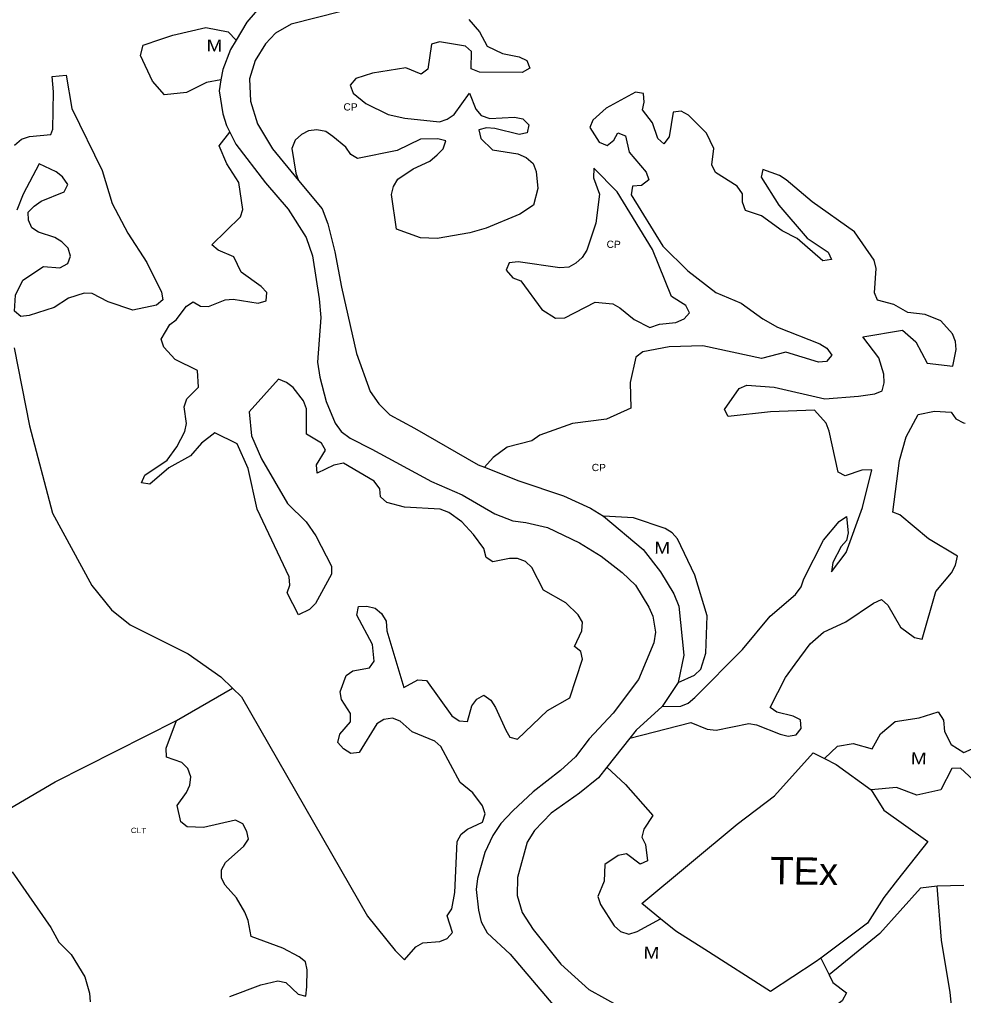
# Model space of a CAD drawing. Extents: x 713589 to 726391, y 7177764 to 7191819.
# Drawn here: x 717458 to 718290, y 7181104 to 7181963 of the extents above; entities that cross this region are included whole.
import ezdxf
from ezdxf.enums import TextEntityAlignment as Align

# ---------------------------------------------------------------- set-up
doc = ezdxf.new("R2010")
doc.units = 0
doc.header["$LTSCALE"] = 2.6
doc.layers.add('63', color=7, linetype='Continuous', lineweight=25)

msp = doc.modelspace()

# ---------------------------------------------------------------- linework, layer by layer
at = {"layer": '63'}
for p, q in [((718038.52, 7181379.7), (718024.45, 7181358.68)), ((717596.72, 7181346.37), (717646, 7181374.88)), ((717995.75, 7181330.77), (717975.51, 7181305.21)), ((718163.9, 7181137.12), (718171.33, 7181122.3))]:
    msp.add_line(p, q, dxfattribs=at)
for points in [[(717832.29, 7182049.62), (717822.19, 7182036.26), (717808.38, 7182023.48), (717791.72, 7182013.22), (717747.47, 7182003.66), (717710.05, 7181989.56), (717687, 7181983.32), (717671.45, 7181976), (717658.76, 7181961.01), (717649.2, 7181945.23)], [(717741.68, 7181970.44), (717697.69, 7181959.42), (717683.97, 7181951.56), (717674.94, 7181942.01), (717665.85, 7181927.27), (717660.97, 7181911.4), (717661.78, 7181891.57), (717667.94, 7181871.61), (717681.14, 7181849.59), (717704.26, 7181821.83)], [(717854.24, 7181963.52), (717863.45, 7181952.66), (717870.36, 7181940.15), (717883.85, 7181933.57), (717898.33, 7181930.61), (717905.24, 7181927.31), (717907.87, 7181920.73), (717900.96, 7181916.79), (717863.44, 7181917.12), (717856.2, 7181920.08), (717856.53, 7181935.22), (717851.27, 7181940.16), (717828.24, 7181943.78), (717821.32, 7181941.81), (717818.03, 7181919.76), (717812.11, 7181915.48), (717798.62, 7181921.08), (717769.33, 7181916.15), (717754.52, 7181911.55), (717749.58, 7181905.62), (717752.21, 7181898.71), (717763.4, 7181889.5), (717783.14, 7181879.95), (717797.62, 7181876.66), (717828.22, 7181873.36), (717835.13, 7181875.66), (717841.06, 7181879.94), (717854.55, 7181898.69), (717860.14, 7181884.54), (717865.08, 7181878.95), (717872.65, 7181876.31), (717894.37, 7181877.63), (717901.61, 7181875.98), (717906.87, 7181870.71), (717905.55, 7181863.8), (717898.31, 7181862.16), (717876.92, 7181867.43), (717869.69, 7181868.09), (717862.77, 7181866.44), (717864.75, 7181858.88), (717874.95, 7181848.67), (717897.32, 7181845.38), (717904.56, 7181842.09), (717910.81, 7181836.82), (717913.44, 7181829.58), (717914.76, 7181814.77), (717911.14, 7181799.96), (717898.96, 7181792.07), (717869.34, 7181779.9), (717854.86, 7181775.62), (717826.23, 7181770.69), (717811.42, 7181771.35), (717790.36, 7181778.92), (717786.09, 7181809.53), (717787.74, 7181816.44), (717791.69, 7181823.02), (717805.18, 7181831.9), (717819.66, 7181838.81)], [(717635.89, 7181910.36), (717623.2, 7181908.13), (717605.42, 7181899.25), (717586.01, 7181897.28), (717575.48, 7181909.13), (717564.95, 7181931.84), (717567.26, 7181941.05), (717582.95, 7181946.14), (717593.59, 7181949.6), (717622.55, 7181956.51), (717642.29, 7181952.55), (717649.2, 7181945.23)], [(717649.2, 7181945.23), (717644.23, 7181937.01), (717637.44, 7181919.46), (717635.89, 7181910.36)], [(717454.18, 7181852.88), (717460.1, 7181858.14), (717467.34, 7181860.44), (717486, 7181862.13), (717487.94, 7181867.02), (717488.28, 7181899.93), (717487.14, 7181913.35), (717499.48, 7181914.47), (717504.53, 7181885.12), (717531.17, 7181830.49), (717540.05, 7181801.53), (717553.87, 7181775.53), (717570.65, 7181749.53), (717583.48, 7181723.53), (717584.79, 7181716.62), (717579.2, 7181712.01), (717558.14, 7181707.74), (717536.42, 7181714.98), (717522.6, 7181722.22), (717515.36, 7181722.55), (717501.54, 7181718.28), (717489.03, 7181710.05), (717466.98, 7181702.82), (717459.74, 7181702.16), (717454.15, 7181706.77)], [(717635.89, 7181910.36), (717634.26, 7181900.8), (717637.46, 7181880.44), (717640.74, 7181870.08), (717643.58, 7181864.35)], [(718024.45, 7181358.68), (718040.71, 7181358.99), (718047.29, 7181361.62), (718053.22, 7181366.55), (718095.02, 7181409), (718119.37, 7181438.28), (718141.75, 7181457.36), (718146.69, 7181463.94), (718149, 7181471.18), (718166.44, 7181505.07), (718180.27, 7181521.52), (718186.52, 7181525.8), (718188.16, 7181511.65), (718186.52, 7181504.74), (718181.91, 7181499.47), (718174.67, 7181485.33), (718173.36, 7181477.27), (718186.34, 7181494.25), (718200.6, 7181533.87), (718208.83, 7181566.95), (718200.02, 7181566.6), (718185.54, 7181561.67), (718179.29, 7181564.96), (718171.4, 7181601.16), (718168.76, 7181608.07), (718158.57, 7181619.59), (718119.73, 7181617.95), (718082.55, 7181614.01), (718079.26, 7181620.26), (718092.1, 7181638.69), (718099.01, 7181641.65), (718123.03, 7181639.67), (718167.45, 7181629.46), (718197.07, 7181631.76), (718211.55, 7181634.06), (718218.13, 7181636.69), (718219.78, 7181643.6), (718219.45, 7181651.17), (718215.17, 7181665.65), (718201.12, 7181684.16), (718235.91, 7181690), (718247.75, 7181679.8), (718257.62, 7181661.04), (718280.21, 7181658.36), (718283.29, 7181672.88), (718282.64, 7181680.12), (718280, 7181686.7), (718269.8, 7181698.22), (718255.98, 7181703.81), (718240.52, 7181705.46), (718228.34, 7181712.7), (718213.87, 7181716.33), (718211.23, 7181722.91), (718212.88, 7181744.3), (718210.91, 7181751.54), (718193.8, 7181776.55), (718156.29, 7181802.88), (718133.59, 7181822.3), (718127.67, 7181826.25), (718112.86, 7181831.52), (718111.54, 7181824.61), (718127.01, 7181799.93), (718152.01, 7181770.96), (718170.44, 7181758.78), (718173.4, 7181752.2), (718165.83, 7181750.89), (718143.13, 7181770.64), (718129.96, 7181777.55), (718111.87, 7181790.71), (718097.72, 7181795.32), (718095.09, 7181802.56), (718095.09, 7181810.13), (718090.48, 7181816.71), (718071.4, 7181828.89), (718068.11, 7181835.48), (718069.76, 7181849.95), (718063.51, 7181863.45), (718047.39, 7181879.25), (718041.13, 7181882.87), (718033.89, 7181881.88), (718030.6, 7181860.16), (718025.66, 7181853.91), (718020.4, 7181858.85), (718015.79, 7181872.67), (718006.91, 7181883.86), (718008.56, 7181890.77), (718007.9, 7181898.34), (718000.99, 7181899.66), (717974.99, 7181885.51), (717963.14, 7181874.98), (717960.51, 7181868.4), (717968.73, 7181855.57), (717975.97, 7181852.6), (717981.9, 7181857.21), (717985.19, 7181863.79)], [(717819.66, 7181838.81), (717826.24, 7181844.4), (717831.51, 7181849.67), (717833.81, 7181856.58), (717826.9, 7181858.55), (717811.44, 7181858.23), (717791.03, 7181848.03), (717756.15, 7181841.12), (717750.23, 7181844.75), (717745.95, 7181851), (717734.44, 7181860.54), (717728.18, 7181864.82), (717720.29, 7181866.47), (717713.05, 7181865.48), (717706.79, 7181862.19), (717701.2, 7181857.26), (717698.24, 7181850.02), (717701.85, 7181828.3), (717704.26, 7181821.83)], [(717724.3, 7181590.56), (717711.13, 7181598.46), (717711.14, 7181620.84), (717708.51, 7181627.75), (717699.3, 7181639.6), (717693.7, 7181643.88), (717686.46, 7181646.84), (717660.66, 7181618.17), (717662.76, 7181596.82), (717671.64, 7181576.75), (717694.34, 7181537.26), (717710.79, 7181521.13), (717719.35, 7181508.95), (717733.16, 7181482.3), (717733.16, 7181475.06), (717719.01, 7181449.39), (717713.74, 7181444.13), (717704.25, 7181439.48), (717694.2, 7181458.8), (717696.63, 7181465.52), (717695.98, 7181472.76), (717667.69, 7181532.33), (717659.79, 7181568.2), (717650.26, 7181589.92), (717630.51, 7181599.46), (717618.66, 7181590.58), (717609.12, 7181579.39), (717590.03, 7181568.87), (717573.25, 7181554.39), (717566.01, 7181555.71), (717568.97, 7181562.29), (717588.39, 7181575.45), (717596.95, 7181587.29), (717604.19, 7181600.78), (717605.51, 7181607.69), (717603.53, 7181622.5), (717605.84, 7181629.41), (717616.04, 7181639.94), (717615.06, 7181654.42), (717595.64, 7181664.3), (717585.44, 7181675.16), (717583.14, 7181682.07), (717590.71, 7181694.9), (717596.31, 7181699.18), (717605.52, 7181711.02), (717611.45, 7181714.97), (717617.7, 7181711.02), (717624.94, 7181710.69), (717639.42, 7181716.61), (717646.66, 7181717.27), (717668.71, 7181713.64), (717675.62, 7181715.95), (717676.28, 7181723.18), (717671.34, 7181728.45), (717653.57, 7181740.96), (717647.32, 7181754.45), (717633.5, 7181760.38), (717627.91, 7181764.99), (717653.12, 7181789.85), (717655.23, 7181796.24), (717651.61, 7181819.94), (717641.08, 7181836.39), (717634.18, 7181852.19), (717643.58, 7181864.35)], [(717643.58, 7181864.35), (717648.82, 7181853.77), (717674.97, 7181819.65), (717694.93, 7181796.51), (717710.79, 7181771.67), (717716.4, 7181755.58), (717722.19, 7181717.47), (717723.71, 7181701.14), (717720.98, 7181661.71), (717722.77, 7181648.68), (717728.5, 7181627.23), (717736.53, 7181608.1), (717741.57, 7181600.83), (717749.58, 7181594.87), (717768.73, 7181585.2), (717821.23, 7181556.78), (717848.36, 7181545.02), (717877.01, 7181528.29), (717892.85, 7181522.26), (717904.26, 7181520.77), (717923.41, 7181516.31), (717951.6, 7181502.76), (717970.6, 7181491.17), (717989.16, 7181476.57), (718000.84, 7181465.35), (718012.5, 7181445.98), (718016.05, 7181438.19), (718018.57, 7181424.21), (718017.07, 7181414.78), (718003.55, 7181382.41), (717981.18, 7181352.88), (717960.17, 7181330.2), (717948.16, 7181314.33), (717934.81, 7181302.36), (717910.83, 7181283.44), (717892.76, 7181266.81), (717882.37, 7181255.52), (717875.27, 7181244.97), (717868.14, 7181230.18), (717861.62, 7181207.13), (717860.52, 7181197.61), (717862.6, 7181179.22), (717865.02, 7181169.2), (717870.31, 7181159.52), (717890.61, 7181140.52), (717932.94, 7181090.31)], [(717985.19, 7181863.79), (717992.1, 7181861.16), (717995.39, 7181846.68), (718010.19, 7181829.23), (718012.49, 7181822.32), (718006.24, 7181817.39), (717998.34, 7181816.73), (717997.03, 7181809.16), (718024.99, 7181764.07), (718047.03, 7181742.35), (718071.71, 7181723.26), (718093.75, 7181713.71), (718112.84, 7181699.89), (718126, 7181692.65), (718163.18, 7181677.83), (718169.43, 7181674.21), (718173.71, 7181667.96), (718169.1, 7181662.37), (718161.86, 7181661.71), (718133.24, 7181670.6), (718111.85, 7181665.01), (718060.18, 7181676.21), (718030.57, 7181675.22), (718007.2, 7181670.95), (718001.28, 7181666.34), (717996.01, 7181643.97), (717996.66, 7181621.26), (717975.27, 7181611.72), (717945.33, 7181607.78), (717916.69, 7181597.58), (717909.45, 7181592.65), (717887.73, 7181587.06), (717875.56, 7181577.85), (717867.82, 7181569.44)], [(717454.15, 7181706.77), (717454.81, 7181720.92), (717461.39, 7181734.08), (717479.5, 7181745.93), (717493.97, 7181744.94), (717500.89, 7181748.55), (717503.52, 7181755.14), (717501.22, 7181762.05), (717495.62, 7181767.64), (717489.7, 7181771.59), (717475.22, 7181776.2), (717469.3, 7181780.15), (717466.34, 7181786.73), (717466.01, 7181793.97), (717466.32, 7181794.28), (717471.28, 7181799.24), (717477.53, 7181803.51), (717497.93, 7181811.74), (717500.9, 7181818.32), (717496.29, 7181824.9), (717490.7, 7181829.51), (717475.85, 7181836.5), (717461.61, 7181809.77), (717456.05, 7181795.59)], [(717704.26, 7181821.83), (717725.04, 7181796.88), (717729.99, 7181783.61), (717736.08, 7181758.82), (717741.85, 7181727.72), (717755.07, 7181669.36), (717767.33, 7181635.93), (717774.82, 7181625.12), (717784.57, 7181615.43), (717806.41, 7181603.69), (717862.41, 7181571.57), (717867.82, 7181569.44)], [(717453.79, 7181674.5), (717467.16, 7181605.74), (717487.55, 7181528.74), (717522.09, 7181465.22), (717539.53, 7181443.83), (717555.98, 7181430.66), (717606.98, 7181404.99), (717635.61, 7181384.91), (717646, 7181374.88)], [(717995.75, 7181330.77), (718049.59, 7181344.51), (718064.07, 7181338.58), (718071.97, 7181337.92), (718100.6, 7181343.84), (718107.51, 7181342.52), (718128.24, 7181334.29), (718135.15, 7181332.64), (718142.39, 7181333.63), (718146.67, 7181339.22), (718146.01, 7181346.79), (718139.76, 7181350.08), (718125.28, 7181353.71), (718119.36, 7181357.66), (718132.86, 7181384.31), (718141.45, 7181396.03), (718154.58, 7181413.92), (718166.43, 7181424.12), (718186.17, 7181433.33), (718210.53, 7181449.78), (718217.44, 7181452.74), (718223.03, 7181447.8), (718234.22, 7181428.39), (718246.39, 7181419.5), (718253.3, 7181417.85), (718265.16, 7181459.97), (718278.98, 7181476.42), (718282.6, 7181483), (718284.28, 7181490.93), (718258.91, 7181506.37), (718233.58, 7181527.44), (718227.39, 7181529.67), (718233.26, 7181575.15), (718239.18, 7181596.21), (718249.72, 7181615.62), (718264.2, 7181618.58), (718278.68, 7181617.92), (718282.95, 7181612), (718289.53, 7181608.38), (718291.17, 7181608.08)], [(717646, 7181374.88), (717654.03, 7181367.13), (717764.9, 7181173.95), (717789.24, 7181144), (717797.59, 7181135.77), (717807.47, 7181146.96), (717813.73, 7181150.58), (717828.53, 7181151.89), (717835.12, 7181154.52), (717839.72, 7181159.79), (717835.12, 7181174.27), (717839.07, 7181180.52), (717841.71, 7181195), (717843.69, 7181239.75), (717847.31, 7181246.33), (717852.9, 7181250.61), (717866.07, 7181256.86), (717868.37, 7181264.1), (717866.07, 7181271.34), (717857.52, 7181282.53), (717846.33, 7181291.74), (717829.55, 7181323.34), (717824.29, 7181328.27), (717804.22, 7181336.5), (717793.69, 7181345.72), (717786.78, 7181348.35), (717779.21, 7181347.37), (717772.96, 7181343.42), (717757.48, 7181318.08), (717750.24, 7181317.43), (717743.66, 7181321.38), (717738.73, 7181326.97), (717740.38, 7181334.21), (717749.92, 7181345.07), (717749.92, 7181352.64), (717742.03, 7181364.82), (717740.71, 7181371.73), (717745.98, 7181385.88), (717751.9, 7181390.15), (717766.71, 7181392.78), (717770.66, 7181398.7), (717769.35, 7181413.18), (717755.53, 7181439.18), (717756.85, 7181446.75), (717764.42, 7181447.08), (717771.66, 7181445.1), (717777.25, 7181440.5), (717781.2, 7181433.91), (717781.85, 7181425.36), (717796.98, 7181375.34), (717809.16, 7181382.24), (717816.73, 7181381.59), (717839.1, 7181350.32), (717845.68, 7181346.04), (717852.92, 7181345.38), (717856.87, 7181359.2), (717861.15, 7181365.12), (717867.4, 7181368.74), (717873.33, 7181364.13), (717877.6, 7181357.88), (717886.81, 7181337.81), (717890.1, 7181331.55), (717897.01, 7181329.91), (717923.34, 7181355.24), (717943.09, 7181366.43), (717954.28, 7181400.32), (717952.64, 7181407.23), (717947.05, 7181411.51), (717953.63, 7181425.33), (717954.29, 7181432.9), (717950.34, 7181439.48), (717939.48, 7181450.01), (717919.74, 7181461.2), (717909.54, 7181480.95), (717903.95, 7181486.21), (717897.04, 7181488.85), (717889.8, 7181488.85), (717875.32, 7181485.89), (717869.4, 7181489.84), (717867.43, 7181497.74), (717858.21, 7181510.24), (717848.01, 7181521.11), (717836.5, 7181529.33), (717828.93, 7181532.3), (717797.34, 7181534.28), (717781.87, 7181538.23), (717776.28, 7181543.17), (717775.62, 7181550.41), (717770.69, 7181556.99), (717743.71, 7181572.79), (717735.15, 7181571.14), (717720.67, 7181564.24), (717720.02, 7181571.48), (717727.92, 7181584.31), (717724.3, 7181590.56)], [(717867.82, 7181569.44), (717898.26, 7181557.44), (717937.52, 7181544.28), (717961.3, 7181533.26), (717972.53, 7181526.35)], [(718038.52, 7181379.7), (718052.89, 7181386.3), (718058.49, 7181391.56), (718062.77, 7181405.71), (718064.09, 7181438.62), (718053.24, 7181474.16), (718037.78, 7181506.41), (718033.17, 7181511.68), (718026.92, 7181515.3), (717998.95, 7181524.85), (717972.53, 7181526.35)], [(717972.53, 7181526.35), (717972.61, 7181526.3), (718007.53, 7181496.76), (718022.76, 7181477.19), (718034.58, 7181457.79), (718038.86, 7181447.01), (718043.29, 7181403.84), (718038.52, 7181379.7)], [(718024.45, 7181358.68), (718001.3, 7181337.77), (717995.75, 7181330.77)], [(718167.19, 7181312.85), (718178.61, 7181323.82), (718192.43, 7181326.12), (718209.21, 7181321.51), (718216.45, 7181334.67), (718229.62, 7181345.53), (718250.68, 7181348.81), (718267.46, 7181354.08), (718272.07, 7181346.51), (718273.05, 7181336.64), (718278.65, 7181325.12), (718289.83, 7181318.2), (718305.3, 7181324.78), (718339.19, 7181331.99)], [(717437.8, 7181262.38), (717449.33, 7181268.45), (717489.81, 7181292.46), (717596.72, 7181346.37)], [(717643.59, 7181103.22), (717670.9, 7181113.75), (717686.04, 7181117.04), (717692.95, 7181115.72), (717703.81, 7181105.51), (717710.72, 7181103.54), (717711.38, 7181111.77), (717711.71, 7181126.9), (717710.4, 7181133.81), (717704.8, 7181138.42), (717690.32, 7181145.99), (717662.35, 7181156.2), (717659.72, 7181170.35), (717656.76, 7181177.59), (717649.53, 7181190.1), (717639.66, 7181201.29), (717636.37, 7181207.54), (717636.37, 7181214.78), (717639.99, 7181221.36), (717656.12, 7181235.84), (717660.07, 7181241.76), (717658.75, 7181248.67), (717655.13, 7181255.25), (717648.55, 7181258.54), (717620.58, 7181252.29), (717613.34, 7181252.3), (717606.1, 7181252.63), (717600.51, 7181257.23), (717597.22, 7181271.39), (717605.45, 7181282.9), (717608.41, 7181289.48), (717609.4, 7181296.72), (717606.77, 7181303.96), (717601.5, 7181309.23), (717588.01, 7181314.17), (717587.69, 7181322.06), (717596.72, 7181346.37)], [(718339.19, 7181331.99), (718323.57, 7181307.67), (718315.83, 7181305.37), (718306.94, 7181298.13), (718298.05, 7181294.18), (718286.87, 7181304.38), (718279.3, 7181304.06), (718269.75, 7181285.3), (718248.69, 7181280.7), (718230.59, 7181287.28), (718208.24, 7181285.42)], [(718023.01, 7181171.78), (718006.46, 7181185.25), (718090.38, 7181254.99), (718123.12, 7181280.09), (718157.35, 7181317.78), (718167.19, 7181312.85)], [(718167.19, 7181312.85), (718177.6, 7181307.63), (718208.24, 7181285.42)], [(717975.51, 7181305.21), (717968.19, 7181295.97), (717951.58, 7181282.26), (717926.69, 7181264.78), (717912.02, 7181249.6), (717905.6, 7181239.24), (717896.88, 7181208.26), (717896.73, 7181192.35), (717901.18, 7181177.19), (717910.76, 7181162.32), (717935.07, 7181131.68), (717959.73, 7181109.56), (717987.25, 7181094.37), (718033.83, 7181076.88), (718044.38, 7181072.47), (718067.72, 7181057.05), (718072.15, 7181054.12), (718078.47, 7181047.53), (718081.11, 7181038.35), (718080.28, 7181031.2), (718077.14, 7181023.14), (718054.19, 7180986.8), (718039.34, 7180946.76), (718036.99, 7180936.65)], [(717975.51, 7181305.21), (717992, 7181289.89), (718016.02, 7181262.58), (718008.12, 7181250.73), (718006.47, 7181243.49), (718009.76, 7181237.24), (718011.4, 7181222.76), (718004.82, 7181219.8), (717992.97, 7181229.01), (717985.73, 7181227.37), (717973.89, 7181219.47), (717973.23, 7181205), (717967.63, 7181191.5), (717969.93, 7181184.26), (717982.1, 7181165.51), (717987.7, 7181160.57), (717994.94, 7181158.26), (718002.18, 7181160.57), (718023.01, 7181171.78)], [(718208.24, 7181285.42), (718219.38, 7181267.48), (718258.21, 7181239.83), (718231.53, 7181205.93), (718219.37, 7181190.47), (718204.99, 7181167.91), (718163.9, 7181137.12)], [(717452.09, 7181213.17), (717485.97, 7181164.13), (717493.21, 7181151.29), (717504.07, 7181140.43), (717515.91, 7181120.69), (717520.19, 7181106.21), (717520.84, 7181098.64)], [(718266.4, 7181200.41), (718251.82, 7181198.64), (718215.98, 7181158.87), (718171.33, 7181122.3)], [(718289.81, 7181201.06), (718266.4, 7181200.41)], [(718284.8, 7181046.78), (718282.27, 7181062.19), (718282.17, 7181063.2), (718278.04, 7181106.99), (718270.15, 7181153.06), (718266.4, 7181200.41)], [(718163.9, 7181137.12), (718159.14, 7181133.55), (718119.65, 7181107.89), (718061.92, 7181144.64), (718036.4, 7181160.89), (718023.01, 7181171.78)], [(718171.33, 7181122.3), (718174.6, 7181115.78), (718186.78, 7181106.57), (718182.83, 7181099.66), (718165.05, 7181086.17), (718142.68, 7181087.82), (718130.17, 7181080.25), (718127.21, 7181073.34), (718126.55, 7181065.77), (718129.51, 7181051.29), (718128.85, 7181044.05), (718119.96, 7181031.88), (718103.5, 7181016.09), (718091, 7180997), (718067.3, 7180976.6), (718064.01, 7180970.02), (718073.88, 7180958.83), (718072.23, 7180951.92), (718066.64, 7180947.65), (718045.25, 7180943.7), (718038.99, 7180940.08), (718036.99, 7180936.65)]]:
    msp.add_lwpolyline(points, dxfattribs=at)
msp.add_lwpolyline([(717980.88, 7181713.08), (717987.14, 7181709.78), (717999.64, 7181699.25), (718013.46, 7181692.34), (718022.01, 7181695.3), (718036.49, 7181696.61), (718043.73, 7181699.9), (718048.34, 7181705.17), (718045.05, 7181711.75), (718032.55, 7181719.65), (718015.77, 7181761.11), (717984.85, 7181811.8), (717964.12, 7181832.53), (717963.79, 7181823.98), (717969.05, 7181809.83), (717965.87, 7181784.2), (717957.86, 7181760.47), (717953.91, 7181753.89), (717948.31, 7181748.95), (717942.06, 7181745.33), (717934.16, 7181745), (717897.64, 7181750.28), (717889.74, 7181749.29), (717887.1, 7181742.71), (717892.7, 7181736.13), (717899.94, 7181733.49), (717918.36, 7181708.15), (717930.53, 7181700.58), (717938.76, 7181700.91), (717965.42, 7181714.72)], close=True, dxfattribs=at)

# ---------------------------------------------------------------- texts
for s, height, width, p in [('M', 10.4, 1.2, (717629.96, 7181935.33)), ('CP', 6.4, 1.05, (717749.9, 7181883.34)), ('CP', 6.4, 1.05, (717981.59, 7181762.39)), ('CP', 6.4, 1.05, (717968.49, 7181565.86)), ('M', 10.4, 1.2, (718024.33, 7181493.2)), ('M', 10.4, 1.2, (718250.19, 7181307.73)), ('CLT', 4.64, 1.15, (717563.18, 7181247.22)), ('TEx', 24, 1.05, (718149.18, 7181201.86)), ('M', 10.4, 1.2, (718014.81, 7181136.71))]:
    msp.add_text(s, height=height, rotation=359.062, dxfattribs=dict(at, width=width)).set_placement(p, align=Align.CENTER)

doc.saveas('drawing.dxf')
